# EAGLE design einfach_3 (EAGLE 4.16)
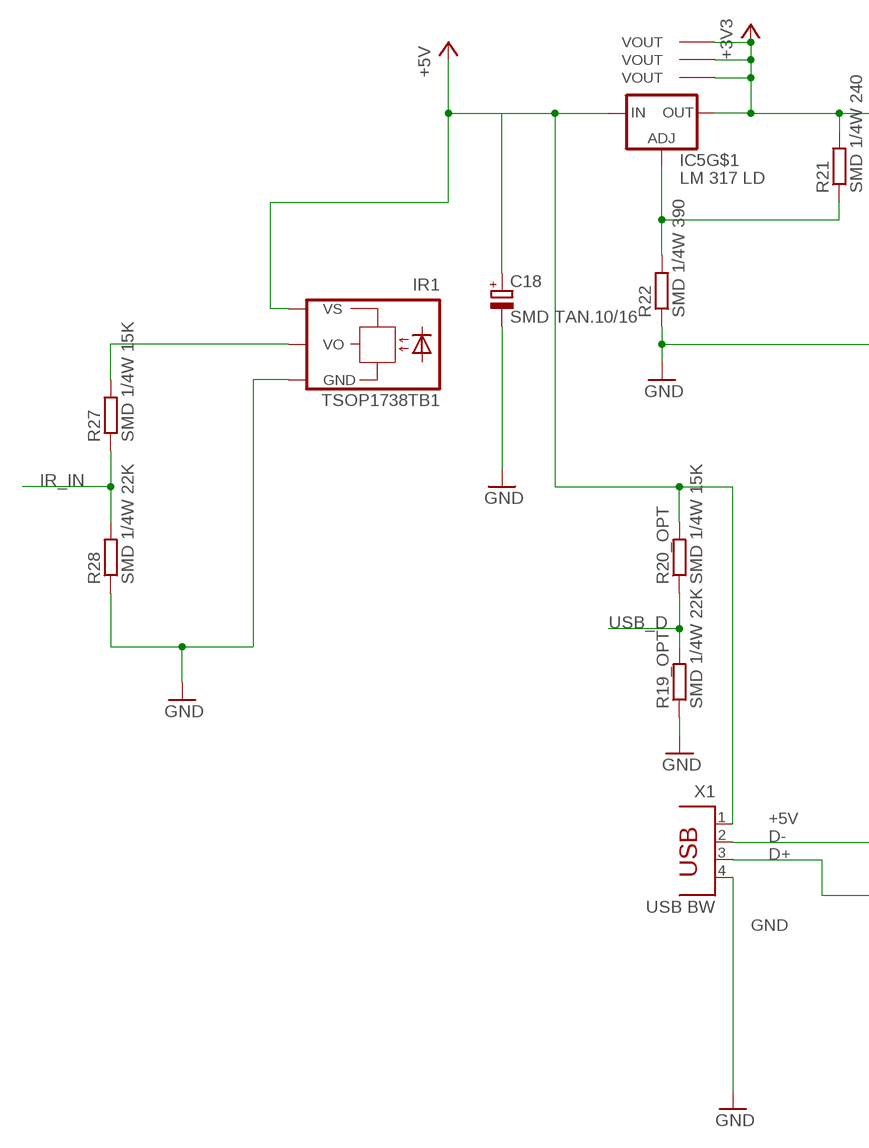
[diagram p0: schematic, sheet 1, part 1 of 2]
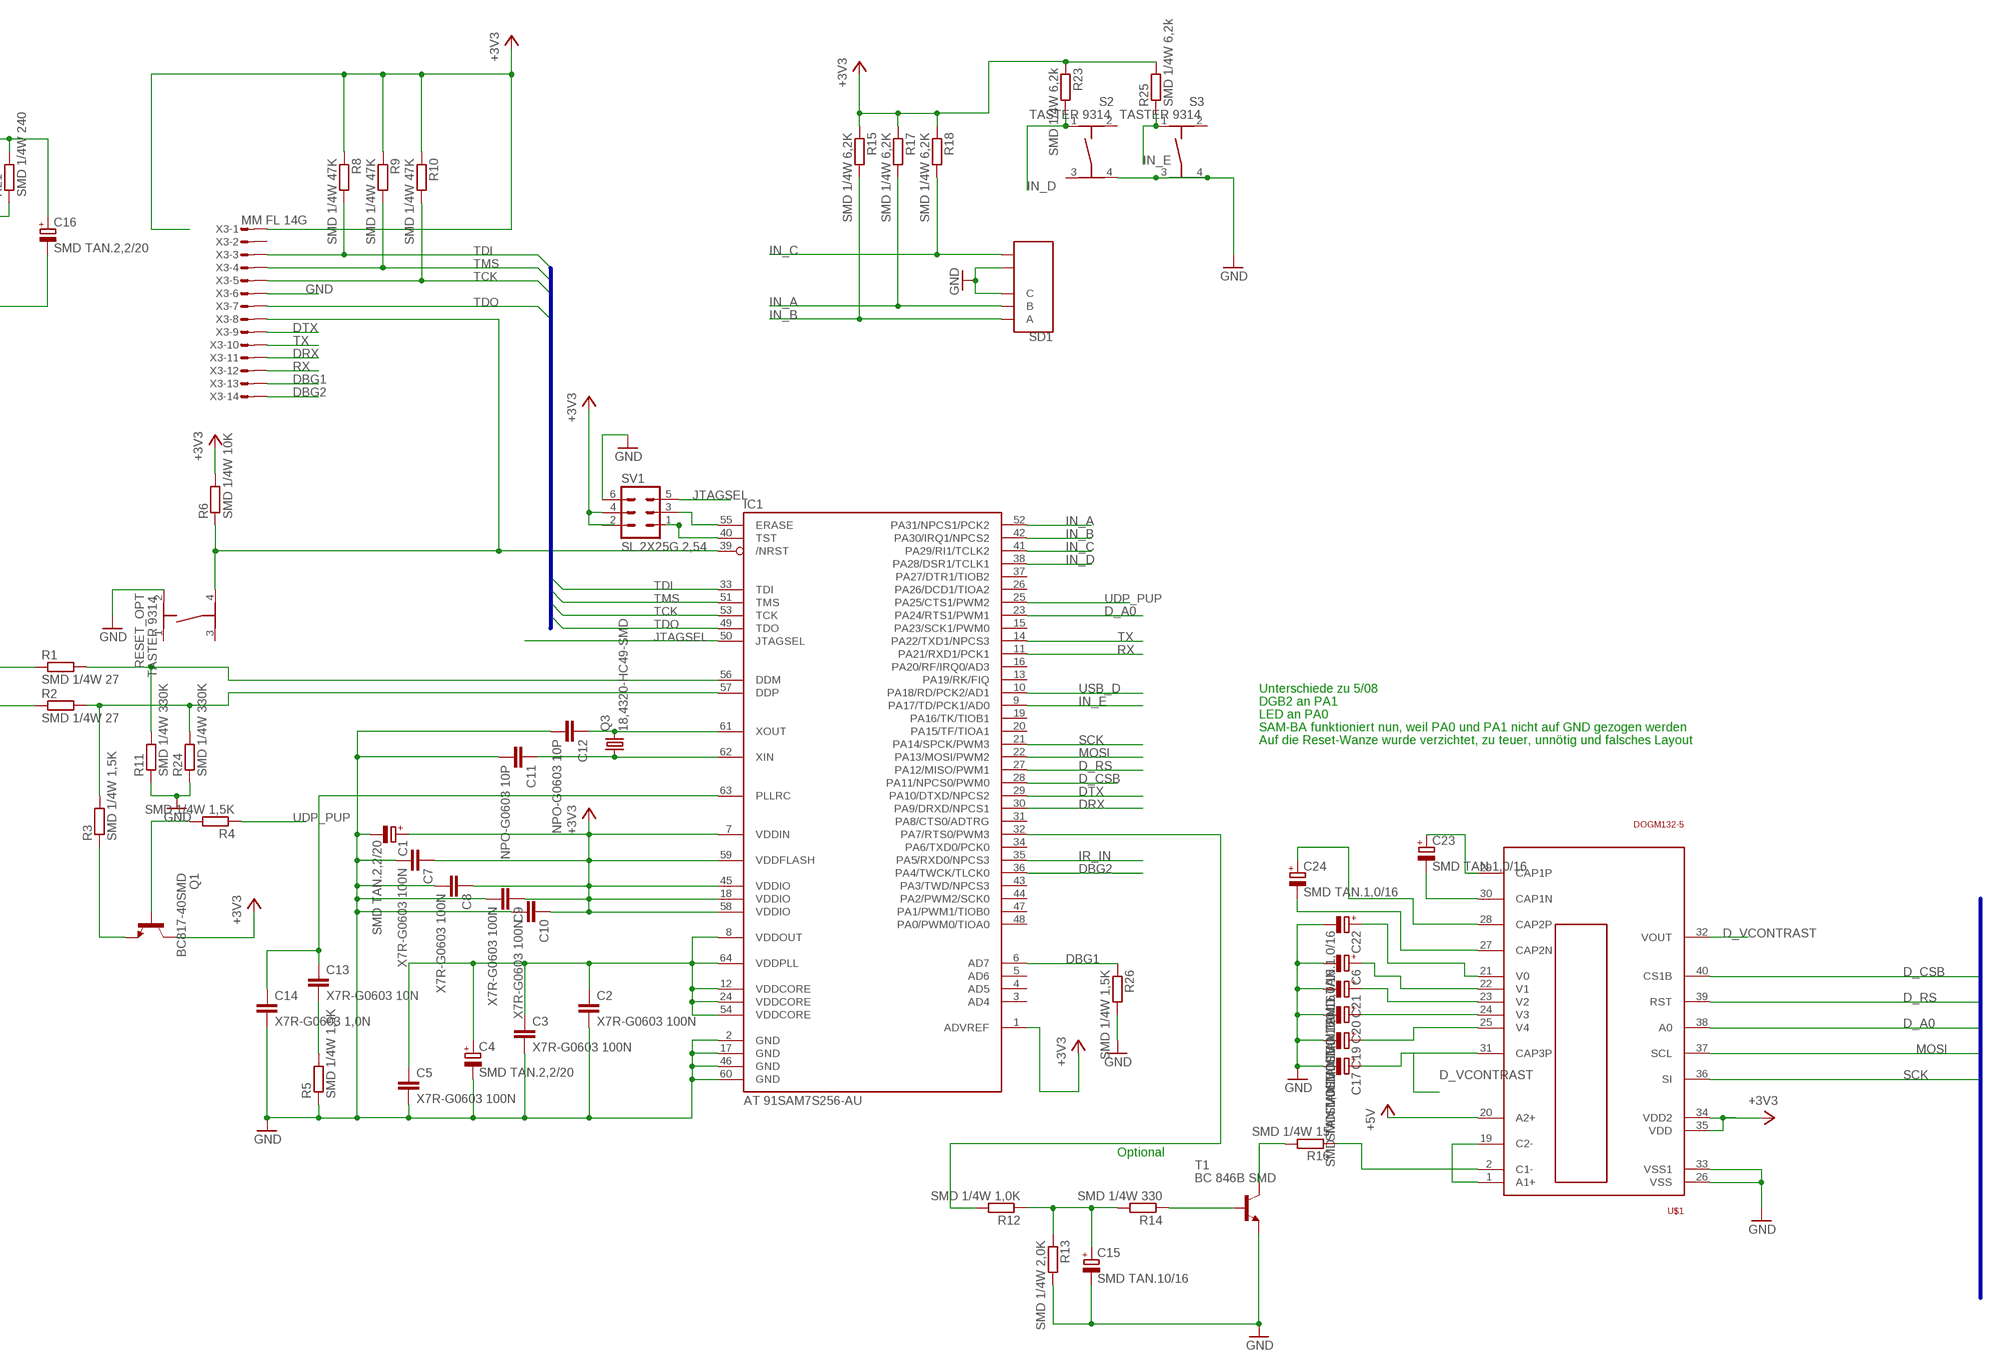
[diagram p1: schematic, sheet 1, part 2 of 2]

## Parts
C1  SMD TAN.2,2/20  CPOL-EUCT3528  [CT3528]
C2  X7R-G0603 100N  C-EUC0603  [C0603]
C3  X7R-G0603 100N  C-EUC0603  [C0603]
C4  SMD TAN.2,2/20  CPOL-EUCT3528  [CT3528]
C5  X7R-G0603 100N  C-EUC0603  [C0603]
C6  SMD TAN.1,0/16  CPOL-EUCT3216  [CT3216]
C7  X7R-G0603 100N  C-EUC0603  [C0603]
C8  X7R-G0603 100N  C-EUC0603  [C0603]
C9  X7R-G0603 100N  C-EUC0603  [C0603]
C10  X7R-G0603 100N  C-EUC0603  [C0603]
C11  NPO-G0603 10P  C-EUC0603  [C0603]
C12  NPO-G0603 10P  C-EUC0603  [C0603]
C13  X7R-G0603 10N  C-EUC0603  [C0603]
C14  X7R-G0603 1,0N  C-EUC0603  [C0603]
C15  SMD TAN.10/16  CPOL-EUCT7343  [CT7343]
C16  SMD TAN.2,2/20  CPOL-EUCT3528  [CT3528]
C17  SMD TAN.1,0/16  CPOL-EUCT3216  [CT3216]
C18  SMD TAN.10/16  CPOL-EUCT7343  [CT7343]
C19  SMD TAN.1,0/16  CPOL-EUCT3216  [CT3216]
C20  SMD TAN.1,0/16  CPOL-EUCT3216  [CT3216]
C21  SMD TAN.1,0/16  CPOL-EUCT3216  [CT3216]
C22  SMD TAN.1,0/16  CPOL-EUCT3216  [CT3216]
C23  SMD TAN.1,0/16  CPOL-EUCT3216  [CT3216]
C24  SMD TAN.1,0/16  CPOL-EUCT3216  [CT3216]
IC1  AT 91SAM7S256-AU  AT91SAM7S512/256/128/64/321  [LQFP64_GOOD]
IC5  LM 317 LD  LM317-SO08  [SO-08]
IR1  TSOP1738TB1  [TSOP17_TB1]
Q1  BC817-40SMD  [SOT23-BEC]
Q3  18,4320-HC49-SMD  CRYSTALHC49UP  [HC49UP]
R1  SMD 1/4W 27  R-EU_R1206W  [R1206W]
R2  SMD 1/4W 27  R-EU_R1206W  [R1206W]
R3  SMD 1/4W 1,5K  R-EU_R1206W  [R1206W]
R4  SMD 1/4W 1,5K  R-EU_R1206W  [R1206W]
R5  SMD 1/4W 1,5K  R-EU_R1206W  [R1206W]
R6  SMD 1/4W 10K  R-EU_R1206W  [R1206W]
R8  SMD 1/4W 47K  R-EU_R1206W  [R1206W]
R9  SMD 1/4W 47K  R-EU_R1206W  [R1206W]
R10  SMD 1/4W 47K  R-EU_R1206W  [R1206W]
R11  SMD 1/4W 330K  R-EU_R1206W  [R1206W]
R12  SMD 1/4W 1,0K  R-EU_R1206W  [R1206W]
R13  SMD 1/4W 2,0K  R-EU_R1206W  [R1206W]
R14  SMD 1/4W 330  R-EU_R1206W  [R1206W]
R15  SMD 1/4W 6,2K  R-EU_R1206W  [R1206W]
R16  SMD 1/4W 15  R-EU_R1206W  [R1206W]
R17  SMD 1/4W 6,2K  R-EU_R1206W  [R1206W]
R18  SMD 1/4W 6,2K  R-EU_R1206W  [R1206W]
R19_OPT  SMD 1/4W 22K  R-EU_R1206W  [R1206W]
R20_OPT  SMD 1/4W 15K  R-EU_R1206W  [R1206W]
R21  SMD 1/4W 240  R-EU_R1206W  [R1206W]
R22  SMD 1/4W 390  R-EU_R1206W  [R1206W]
R23  SMD 1/4W 6,2k  R-EU_R1206W  [R1206W]
R24  SMD 1/4W 330K  R-EU_R1206W  [R1206W]
R25  SMD 1/4W 6,2k  R-EU_R1206W  [R1206W]
R26  SMD 1/4W 1,5K  R-EU_R1206W  [R1206W]
R27  SMD 1/4W 15K  R-EU_R1206W  [R1206W]
R28  SMD 1/4W 22K  R-EU_R1206W  [R1206W]
RESET_OPT  TASTER 9314  TASTER-9314_SMD  [TASTER-9314_SMD]
S2  TASTER 9314  TASTER-9314_SMD  [TASTER-9314_SMD]
S3  TASTER 9314  TASTER-9314_SMD  [TASTER-9314_SMD]
SD1  STEC12E08  STEC12D08  [EC12E08]
SV1  SL 2X25G 2,54  MA03-2  [MA03-2]
T1  BC 846B SMD  BC846  [SOT23]
U$1  DOGM132-5  [DOGM]
X1  USB BW  PN61729  [PN61729]
X3  MM FL 14G  MICROMATCH-14  [MICROMATCH-14]

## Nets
1.8V: C2.1 C3.1 C4.+ C5.1 IC1.8(VDDOUT) IC1.12(VDDCORE) IC1.24(VDDCORE) IC1.54(VDDCORE) IC1.64(VDDPLL)
+3V3: C1.+ C7.1 C8.1 C9.1 C10.1 C16.+ IC1.1(ADVREF) IC1.7(VDDIN) IC1.18(VDDIO) IC1.45(VDDIO) IC1.58(VDDIO) IC1.59(VDDFLASH) IC5.2(OUT) IC5.3(VOUT) IC5.6(VOUT) IC5.7(VOUT) Q1.C R6.2 R8.1 R9.1 R10.1 R15.1 R17.1 R18.1 R21.2 R23.1 R25.2 SV1.2 SV1.4 U$1.34(VDD2) U$1.35(VDD) X3.1
+5V: C18.+ IC5.1(IN) IR1.VS R20_OPT.2 U$1.20(A2+) X1.1
D+: R2.1 X1.3
D-: R1.1 X1.2
D_A0: IC1.23(PA24/RTS1/PWM1) U$1.38(A0)
D_CSB: IC1.28(PA11/NPCS0/PWM0) U$1.40(CS1B)
D_RS: IC1.27(PA12/MISO/PWM1) U$1.39(RST)
D_VCONTRAST: C17.+ U$1.31(CAP3P) U$1.32(VOUT)
DBG1: IC1.6(AD7) R26.1 X3.13
DBG2: IC1.36(PA4/TWCK/TLCK0) X3.14
DDM: IC1.56(DDM) R1.2 R11.2
DDP: IC1.57(DDP) R2.2 R3.2 R24.2
DRX: IC1.30(PA9/DRXD/NPCS1) X3.11
DTX: IC1.29(PA10/DTXD/NPCS2) X3.9
GND: C1.- C2.2 C3.2 C4.- C5.2 C6.- C7.2 C8.2 C9.2 C10.2 C11.2 C12.2 C14.2 C15.- C16.- C17.- C18.- C19.- C20.- C21.- C22.- IC1.2(GND) IC1.17(GND) IC1.46(GND) IC1.60(GND) IR1.GND R5.1 R11.1 R13.2 R19_OPT.1 R22.1 R24.1 R26.2 R28.1 RESET_OPT.2 S2.4 S3.3 S3.4 SD1.C SD1.D(S1) SV1.6 T1.2(E) U$1.26(VSS) U$1.33(VSS1) X1.4 X3.6
IN_A: IC1.52(PA31/NPCS1/PCK2) R17.2 SD1.B
IN_B: IC1.42(PA30/IRQ1/NPCS2) R15.2 SD1.A
IN_C: IC1.41(PA29/RI1/TCLK2) R18.2 SD1.E(S2)
IN_D: IC1.38(PA28/DSR1/TCLK1) R23.2 S2.1
IN_E: IC1.9(PA17/TD/PCK1/AD0) R25.1 S3.1
IR_IN: IC1.35(PA5/RXD0/NPCS3) R27.1 R28.2
JTAGSEL: IC1.50(JTAGSEL) SV1.5
LED: IC1.32(PA7/RTS0/PWM3) R12.2
MOSI: IC1.22(PA13/MOSI/PWM2) U$1.36(SI)
N$1: U$1.1(A1+) U$1.19(C2-)
N$2: R16.1 U$1.2(C1-)
N$3: Q1.E R3.1
N$4: Q1.B R4.2
N$5: IR1.VO R27.2
N$6: IC1.40(TST) SV1.1
N$7: C11.1 IC1.62(XIN) Q3.1
N$8: C12.1 IC1.61(XOUT) Q3.2
N$9: C13.1 C14.1 IC1.63(PLLRC)
N$10: C13.2 R5.2
N$11: IC1.39(/NRST) R6.1 RESET_OPT.4 X3.8
N$12: IC1.55(ERASE) SV1.3
N$13: C6.+ U$1.22(V1)
N$14: C19.+ U$1.25(V4)
N$15: C20.+ U$1.24(V3)
N$16: C21.+ U$1.23(V2)
N$17: C22.+ U$1.21(V0)
N$21: C24.+ U$1.28(CAP2P)
N$22: C24.- U$1.27(CAP2N)
N$23: C23.- U$1.30(CAP1N)
N$24: C23.+ U$1.29(CAP1P)
N$31: R16.2 T1.3(C)
N$32: R14.1 T1.1(B)
N$33: C15.+ R12.1 R13.1 R14.2
N$40: IC5.4(ADJ) R21.1 R22.2
RX: IC1.11(PA21/RXD1/PCK1) X3.12
SCK: IC1.21(PA14/SPCK/PWM3) U$1.37(SCL)
TCK: IC1.53(TCK) R10.2 X3.5
TDI: IC1.33(TDI) R8.2 X3.3
TDO: IC1.49(TDO) X3.7
TMS: IC1.51(TMS) R9.2 X3.4
TX: IC1.14(PA22/TXD1/NPCS3) X3.10
UDP_PUP: IC1.25(PA25/CTS1/PWM2) R4.1
USB_D: IC1.10(PA18/RD/PCK2/AD1) R19_OPT.2 R20_OPT.1
Unconnected: IC1.3(AD4) IC1.4(AD5) IC1.5(AD6) IC1.13(PA19/RK/FIQ) IC1.15(PA23/SCK1/PWM0) IC1.16(PA20/RF/IRQ0/AD3) IC1.19(PA16/TK/TIOB1) IC1.20(PA15/TF/TIOA1) IC1.26(PA26/DCD1/TIOA2) IC1.31(PA8/CTS0/ADTRG) IC1.34(PA6/TXD0/PCK0) IC1.37(PA27/DTR1/TIOB2) IC1.43(PA3/TWD/NPCS3) IC1.44(PA2/PWM2/SCK0) IC1.47(PA1/PWM1/TIOB0) IC1.48(PA0/PWM0/TIOA0) RESET_OPT.1 RESET_OPT.3 S2.2 S2.3 S3.2 X3.2

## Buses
B$1
B$2

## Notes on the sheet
- Unterschiede zu 5/08
- DGB2 an PA1
- LED an PA0
- SAM-BA funktioniert nun, weil PA0 und PA1 nicht auf GND gezogen werden
- Auf die Reset-Wanze wurde verzichtet, zu teuer, unnötig und falsches Layout
- Optional

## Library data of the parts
C1 C4 C6 C15-C24 = rcl:CPOL-EU: POLARIZED CAPACITOR, European symbol
C2 C3 C5 C7-C14 = rcl:C-EU: CAPACITOR, European symbol
IC1 = at91sam7sxxx-au:AT91SAM7S512/256/128/64/321
IC5 = v-reg:LM317-SO08
IR1 = telefunken:TSOP17*TB1: TSOP17..TB1 IR Receiver Modules for Remote Control Systems Source: http://www.vishay.com/docs/82042/82042.pdf
Q1 = transistor-npn:BC817*: NPN Transistor
Q3 = crystal:CRYSTAL: CRYSTAL
R1-R6 R8-R18 R19_OPT R20_OPT R21-R28 = rcl:R-EU_: RESISTOR, European symbol
RESET_OPT S2 S3 = Ergaenzung:TASTER-9314_SMD
SD1 = piher:STEC12D08
SV1 = con-lstb:MA03-2: PIN HEADER
T1 = transistor:BC846: NPN TRANSISTOR
U$1 = opto:DOGM132-5
X1 = con-berg:PN61729: BERG USB connector
X3 = con-amp-micromatch:MICROMATCH-14: MicroMaTch 14 8-215464-4 / 1-215464-4 Drawing Number C-215464 DDEController.pdf

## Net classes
0 default: width 0.203 mm, drill 0.203 mm, clearance 0.6 mm
1 GND: width 0.203 mm, drill 0.203 mm, clearance 0.6 mm

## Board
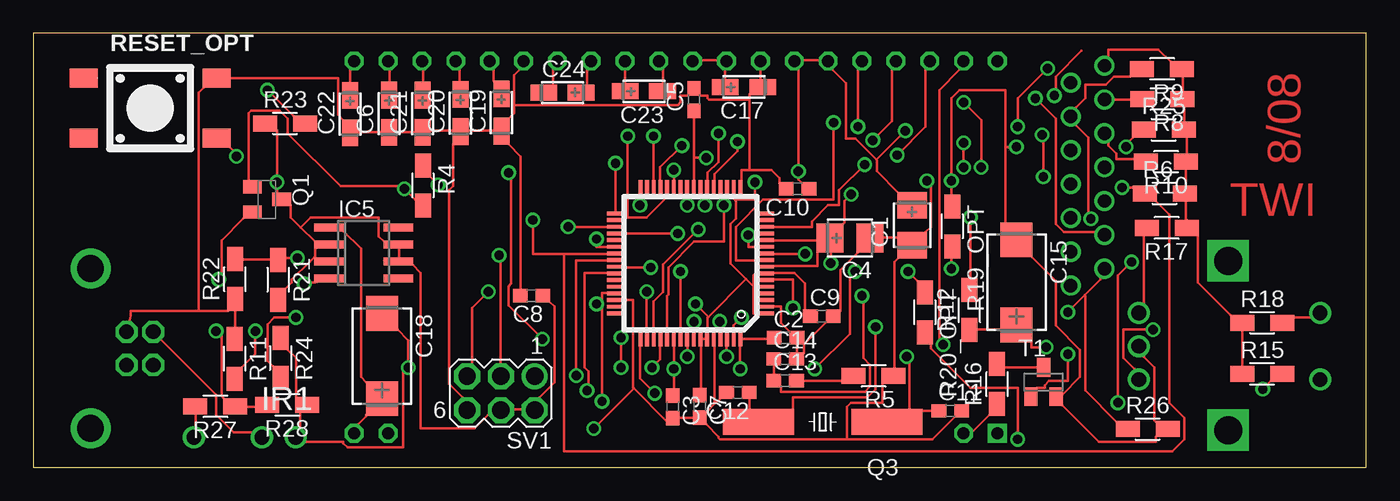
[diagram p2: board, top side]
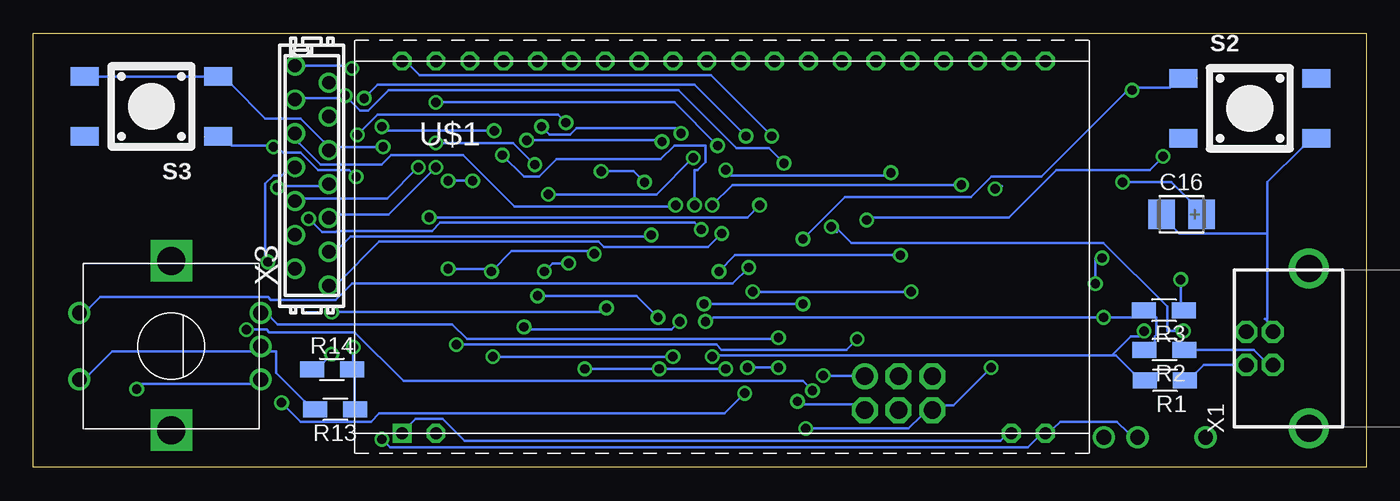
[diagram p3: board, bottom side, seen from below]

Size 100 x 32.6 mm. Coordinates in mm from the lower left corner, seen from the top.
Outline: 0,0 100,0 100,32.6 0,32.6 0,0
Copper layers (1*16): Top 0.035mm / dielectric 1.5mm / Bottom 0.035mm
Design rules "8mils": minimum track width 8mil, minimum drill 0.7mm, track to track 8mil, track to pad 8mil, pad to pad 8mil, via to via 8mil, smd to smd 8mil, copper to edge 40mil, drill to drill 10mil, minimum pad ring 10mil, minimum via ring 8mil, stop-mask expansion 0mil, vias tented up to drill 0mil, thermal gap 10mil

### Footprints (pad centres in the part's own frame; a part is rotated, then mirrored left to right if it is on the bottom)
CT3528 = smd 2 x 2.2: + 1.5,0; - -1.5,0
C0603 = smd 1.1 x 1: 1 -0.85,0; 2 0.85,0
CT3216 = smd 2 x 1.2: + 1.4,0; - -1.4,0
CT7343 = smd 2.6 x 2.4: + 3.2,0; - -3.2,0
LQFP64_GOOD = smd 1.1 x 0.285: 1 -5.7,3.75; 2 -5.7,3.25; 3 -5.7,2.75; 4 -5.7,2.25; 5 -5.7,1.75; 6 -5.7,1.25; 7 -5.7,0.75; 8 -5.7,0.25; 9 -5.7,-0.25; 10 -5.7,-0.75; 11 -5.7,-1.25; 12 -5.7,-1.75; 13 -5.7,-2.25; 14 -5.7,-2.75; 15 -5.7,-3.25; 16 -5.7,-3.75; 33 5.7,-3.75; 34 5.7,-3.25; 35 5.7,-2.75; 36 5.7,-2.25; 37 5.7,-1.75; 38 5.7,-1.25; 39 5.7,-0.75; 40 5.7,-0.25; 41 5.7,0.25; 42 5.7,0.75; 43 5.7,1.25; 44 5.7,1.75; 45 5.7,2.25; 46 5.7,2.75; 47 5.7,3.25; 48 5.7,3.75 | smd 0.285 x 1.1: 17 -3.75,-5.7; 18 -3.25,-5.7; 19 -2.75,-5.7; 20 -2.25,-5.7; 21 -1.75,-5.7; 22 -1.25,-5.7; 23 -0.75,-5.7; 24 -0.25,-5.7; 25 0.25,-5.7; 26 0.75,-5.7; 27 1.25,-5.7; 28 1.75,-5.7; 29 2.25,-5.7; 30 2.75,-5.7; 31 3.25,-5.7; 32 3.75,-5.7; 49 3.75,5.7; 50 3.25,5.7; 51 2.75,5.7; 52 2.25,5.7; 53 1.75,5.7; 54 1.25,5.7; 55 0.75,5.7; 56 0.25,5.7; 57 -0.25,5.7; 58 -0.75,5.7; 59 -1.25,5.7; 60 -1.75,5.7; 61 -2.25,5.7; 62 -2.75,5.7; 63 -3.25,5.7; 64 -3.75,5.7
SO-08 = smd 0.6 x 2.2: 1 -1.905,-2.6; 2 -0.635,-2.6; 3 0.635,-2.6; 4 1.905,-2.6; 5 1.905,2.6; 6 0.635,2.6; 7 -0.635,2.6; 8 -1.905,2.6
TSOP17_TB1 = drill 1.1 pad 1.676 round: GND 0,-3.81; VO 0,3.81; VS 0,-1.27
SOT23-BEC = smd 1 x 1.4: B -0.95,-1.1; C 0,1.1; E 0.95,-1.1
HC49UP = smd 5.334 x 1.93: 1 -4.826,0; 2 4.826,0
R1206W = smd 1.8 x 1.2: 1 -1.499,0; 2 1.499,0
TASTER-9314_SMD = smd 2.1 x 1.4: 1 -5,2.25; 2 5,2.25; 3 -5,-2.25; 4 5,-2.25
EC12E08 = drill 1.1 round: A -2.5,-6.7; B 2.5,-6.7; C 0,-6.7; D -2.5,6.9; E 2.5,6.9 | drill 2.1 square: P$1 -6.3,0; P$2 6.4,0
MA03-2 = drill 1.3 round: 1 -2.54,-1.27 | drill 1.3 octagon: 2 -2.54,1.27; 3 0,-1.27; 4 0,1.27; 5 2.54,-1.27; 6 2.54,1.27
SOT23 = smd 1 x 1.4: 1 -0.95,-1.1; 2 0.95,-1.1; 3 0,1.1
DOGM = drill 0.9 square: 1 -22.86,-13.97 | drill 0.9 octagon: 2 -20.32,-13.97; 19 22.86,-13.97; 20 25.4,-13.97; 21 25.4,13.97; 22 22.86,13.97; 23 20.32,13.97; 24 17.78,13.97; 25 15.24,13.97; 26 12.7,13.97; 27 10.16,13.97; 28 7.62,13.97; 29 5.08,13.97; 30 2.54,13.97; 31 0,13.97; 32 -2.54,13.97; 33 -5.08,13.97; 34 -7.62,13.97; 35 -10.16,13.97; 36 -12.7,13.97; 37 -15.24,13.97; 38 -17.78,13.97; 39 -20.32,13.97; 40 -22.86,13.97
PN61729 = drill 1.1 octagon: 1 1.25,4.71; 2 -1.25,4.71; 3 -1.25,2.71; 4 1.25,2.71 | drill 2 round: P$1 -6,0; P$2 6,0
MICROMATCH-14 = drill 1 round: 1 8.255,1.27; 2 6.985,-1.27; 3 5.715,1.27; 4 4.445,-1.27; 5 3.175,1.27; 6 1.905,-1.27; 7 0.635,1.27; 8 -0.635,-1.27; 9 -1.905,1.27; 10 -3.175,-1.27; 11 -4.445,1.27; 12 -5.715,-1.27; 13 -6.985,1.27; 14 -8.255,-1.27

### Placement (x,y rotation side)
C1  65.93,18.19 90 top
C2  56.44,9.74 0 top
C3  47.98,4.56 270 top
C4  61.27,17.23 180 top
C5  49.57,27.62 90 top
C6  26.69,26.56 90 top
C7  49.99,4.6 270 top
C8  37.38,12.91 180 top
C9  59.15,11.37 0 top
C10  57.35,20.92 180 top
C11  68.79,4.25 0 top
C12  52.86,5.64 180 top
C13  56.41,6.52 0 top
C14  56.41,8.15 0 top
C15  73.76,13.91 270 top
C16  13.85,19.01 0 bottom
C17  53.32,28.57 180 top
C18  26.15,8.36 270 top
C19  35.11,26.66 90 top
C20  32.04,26.62 90 top
C21  29.21,26.56 90 top
C22  23.77,26.53 90 top
C23  45.81,28.24 180 top
C24  39.69,28.14 0 top
IC1  49.3,15.33 180 top
IC5  24.78,16.11 270 top
IR1  15.87,2.27 90 top
Q1  17.53,20.13 270 top
Q3  59.22,3.42 180 top
R1  15.1,6.55 180 bottom
R2  15.15,8.85 180 bottom
R3  15.18,11.8 180 bottom
R4  29.23,21.17 270 top
R5  63.02,6.88 180 top
R6  84.88,20.59 0 top
R8  84.7,27.65 180 top
R9  84.68,29.92 180 top
R10  84.98,22.95 180 top
R11  15.1,8.16 270 top
R12  70.23,11.84 90 top
R13  77.34,4.37 180 bottom
R14  77.6,7.37 0 bottom
R15  92.2,7.04 0 top
R16  72.31,6.27 90 top
R17  85.03,17.99 180 top
R18  92.2,10.87 0 top
R19_OPT  68.94,18.08 270 top
R20_OPT  66.88,11.64 270 top
R21  18.36,14.09 270 top
R22  15.13,14.15 90 top
R23  18.89,25.84 0 top
R24  18.56,8.22 270 top
R25  84.81,25.36 0 top
R26  83.6,2.89 0 top
R27  13.66,4.59 180 top
R28  19.04,4.7 180 top
RESET_OPT  8.77,26.98 0 top
S2  8.73,26.96 0 bottom
S3  91.13,27.11 180 bottom
SD1  89.65,9.11 90 bottom
SV1  35.08,5.58 180 top
T1  75.79,6.42 0 top
U$1  49.47,16.55 0 bottom
X1  4.29,8.94 90 bottom
X3  79.1,21.91 90 bottom

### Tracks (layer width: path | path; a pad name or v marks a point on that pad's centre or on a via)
1.8V  (via drill 0.7)
  Top 0.203: C2.1 55.06,9.64 53.13,9.64 IC1.64 53.03,9.13 v53.03,7.4 | C3.1 48.05,5.88 v48.05,7.4 48.05,9.13 IC1.54 | 49.57,23.25 49.57,26.3 C5.1 | 49.57,23.25 49.57,21.53 IC1.24 | IC1.8 55.47,15.13 58.82,15.13 58.82,16.14 C4.+ | IC1.12 55.47,17.06 58.82,17.06 C4.+ | v50.49,23.25 49.57,23.25 | v61.36,20.51 60.85,20 60.85,18.38 60.75,18.28 C4.+ | v58.62,7.4 61.26,10.05 61.26,14.31 v61.66,14.72 | v59.84,15.33 59.84,16.14 C4.+
  Bottom 0.203: v48.05,7.4 v53.03,7.4 v58.62,7.4 | v50.49,23.25 53.23,20.51 v61.36,20.51 | v61.66,14.72 61.05,15.33 v59.84,15.33
+3V3  (via drill 0.7)
  Top 0.203: C8.1 38.7,12.48 39.11,12.08 39.11,6.39 37.99,5.27 SV1.2 36.67,4.36 35.96,4.36 SV1.4 34.13,3.95 33.12,2.93 29.05,2.93 29.05,14.62 28.44,15.23 IC5.6 | v42.67,4.97 42.67,12.28 | 42.67,12.28 42.67,13.09 43.07,13.09 IC1.45 | IC5.6 27.43,15.74 27.43,16.45 IC5.7 26.31,16.95 25.9,17.36 25.9,18.78 20.82,18.78 20.06,18.02 | IC5.6 26.31,15.53 | R15.1 90.72,7.61 90.72,10.35 R18.1 89.81,11.47 87.37,13.91 87.37,17.46 R17.1 | R17.1 86.56,18.58 | C7.1 50.08,5.98 50.08,9.13 IC1.58 50.18,9.64 50.49,9.64 IC1.59 50.59,10.15 50.59,11.27 50.64,11.32 | 54.05,13.6 54.05,14.41 54.25,14.62 54.45,14.62 IC1.7 55.47,14.62 57.09,14.62 57.91,13.81 57.91,11.77 C9.1 | 54.05,13.6 54.05,11.57 54.45,11.57 IC1.1 | 52.67,20.05 52.72,20 52.72,18.68 52.32,18.28 52.32,15.33 53.49,14.16 | 52.67,20.05 52.52,20.21 52.52,20.51 IC1.18 | 53.49,14.16 54.05,13.6 | 50.64,11.32 53.49,14.16 | C10.1 57.7,21.32 57.4,21.63 v57.4,22.24 57.4,29.86 U$1.34 57.7,30.57 59.02,30.57 U$1.35 59.94,29.86 60.95,28.84 60.95,24.68 61.66,24.68 63.24,23.1 | 63.24,23.1 63.29,23.05 63.29,22.24 64.92,20.61 C1.+ | v54.15,21.43 54.15,20.1 52.72,20.1 52.67,20.05 | v76.09,29.96 73.86,27.72 v73.86,25.59 | 63.24,23.1 v65.42,25.29 | 42.67,12.28 v42.26,12.28 | v49.68,12.28 50.64,11.32 | 21.08,15.79 21.13,15.84 21.13,16.45 IC5.2 21.13,16.95 20.06,18.02 | 21.08,15.79 20.77,15.48 | 20.77,15.48 19.4,14.11 19.4,13.91 18.89,13.4 R21.2 | 20.77,15.48 20.72,15.53 | IC5.3 21.13,15.74 21.08,15.79 | R17.1 86.46,18.58 86.46,20 R6.2 86.46,21.12 86.46,22.44 R10.1 86.56,23.46 86.56,24.78 R25.2 86.35,25.89 86.35,27.11 R8.1 86.25,28.23 86.25,29.35 R9.1 85.34,30.47 84.42,31.38 80.66,31.38 80.66,30.87 X3.1
  Top 0.203: R23.1 18.28,25.29 v18.28,21.43 18.28,20.61 Q1.C 19.3,19.7 19.3,18.78 20.06,18.02
  Bottom 0.203: v42.67,4.97 42.46,4.76 38.5,4.76 SV1.2 | v54.15,21.43 54.96,22.24 v57.4,22.24 | v73.86,25.59 73.55,25.29 v65.42,25.29 | v42.26,12.28 v49.68,12.28 | X3.1 79.65,30.16 76.6,30.16 v76.09,29.96 | v18.28,21.43 14.62,21.43 13.3,20.1 C16.+
+5V  (via drill 0.7)
  Top 0.203: v73.86,2.12 73.86,5.98 70.3,5.98 67.35,8.93 67.35,9.33 R20_OPT.2 | X1.1 9.34,9.84 13.71,5.47 13.71,3.95 15.03,2.63 16.35,2.63 IR1.VS | U$1.20 24.38,3.24 24.99,3.85 24.99,3.95 C18.+ 24.99,6.39 24.58,6.79 24.58,16.45 23.26,17.77 IC5.1
  Bottom 0.203: v73.86,2.12 73.25,1.51 25.39,1.51 24.68,2.22 U$1.20 23.46,2.93 22.95,3.44 18.69,3.44 17.88,2.63 IR1.VS
D+
  Bottom 0.203: R2.1 12.79,8.83 8.43,8.83 7.72,8.12 X1.3
D-
  Bottom 0.203: R1.1 12.79,7.1 12.19,7.71 9.75,7.71 X1.2
D_A0  (via drill 0.7)
  Top 0.203: v50.39,19.7 50.08,20 50.08,20.51 IC1.23 | v64.81,23.46 66.95,25.59 66.95,29.86 U$1.38
  Bottom 0.203: v50.39,19.7 50.39,22.34 50.18,22.34 49.57,22.95 49.57,24.17 51.91,24.17 52.93,23.15 60.75,23.15 62.07,21.83 63.19,21.83 v64.81,23.46
D_CSB  (via drill 0.7)
  Top 0.203: v44.6,24.88 44.6,18.78 46.02,18.78 47.54,20.31 47.54,20.51 IC1.28
  Bottom 0.203: v44.6,24.88 49.17,29.45 71.01,29.45 71.72,30.16 U$1.40
D_RS  (via drill 0.7)
  Top 0.203: v48.05,22.34 48.05,21.53 IC1.27 | v35.66,22.14 35.86,21.93 35.86,13.81 35.66,13.6 35.66,12.18 v38.2,9.64 | v68.27,9.23 67.96,9.54 67.96,28.33 69.49,29.86 U$1.39
  Bottom 0.203: v48.05,22.34 47.64,21.93 35.86,21.93 v35.66,22.14 | v38.2,9.64 39.01,8.83 48.35,8.83 48.76,9.23 v68.27,9.23
D_VCONTRAST
  Top 0.203: C17.+ 51.91,29.15 51.91,29.86 U$1.32 51.4,30.57 50.08,30.57 U$1.31
DBG1  (via drill 0.7)
  Top 0.203: v56.99,11.98 56.99,14.11 55.47,14.11 IC1.6 | 78.89,12.94 80.05,14.11 80.05,14.21 X3.13 | v77.62,11.67 78.89,12.94 | R26.1 81.27,3.44 78.94,5.78 78.94,12.89 78.89,12.94
  Bottom 0.203: v56.99,11.98 57.3,11.67 v77.62,11.67
DBG2  (via drill 0.7)
  Top 0.203: v48.35,17.56 44.09,17.56 IC1.36
  Bottom 0.203: v48.35,17.56 49.37,16.55 57.19,16.55 57.6,16.95 74.06,16.95 77.11,13.91 X3.14
DDM  (via drill 0.7)
  Top 0.203: v49.07,8.32 49.07,9.13 IC1.56 | v16.66,10.25 16.66,8.52 15.64,7.51 R11.2
  Bottom 0.203: 48.96,8.42 v49.07,8.32 48.56,8.42 19.09,8.42 | 19.09,8.42 18.79,8.42 17.47,7.1 R1.2 | v16.66,10.25 17.06,9.84 17.67,9.84 19.09,8.42
DDP  (via drill 0.7)
  Top 0.203: v49.57,10.96 49.57,10.15 IC1.57 | v19.7,11.27 18.08,11.27 17.57,10.76 17.57,8.01 17.98,7.61 R24.2
  Bottom 0.203: 49.27,11.27 v49.57,10.96 49.07,11.16 48.96,11.27 v19.7,11.27 17.57,11.27 R3.2 15.84,11.27 15.74,11.27 15.74,9.94 15.84,9.84 15.84,9.44 R2.2
DRX  (via drill 0.7)
  Top 0.203: v46.53,24.88 46.53,21.53 IC1.30 | v75.18,27.72 76.7,26.2 76.7,18.28 77.31,17.67 79.65,17.67 X3.11
  Bottom 0.203: v46.53,24.88 50.39,28.74 74.16,28.74 v75.18,27.72
DTX  (via drill 0.7)
  Top 0.203: v48.66,24.17 47.03,22.54 47.03,21.53 IC1.29 | v69.79,27.42 71.11,26.1 v71.11,22.54
  Bottom 0.203: v48.66,24.17 51.91,27.42 v69.79,27.42 | v71.11,22.54 73.45,20.21 79.65,20.21 X3.9
GND  (via drill 0.7)
  Top 0.203: 72.94,24.07 72.94,18.38 C15.- 74.87,15.84 76.7,14.01 76.7,10.66 78.53,8.83 78.53,6.79 77.21,5.47 T1.2 77.21,4.66 79.95,1.92 84.22,1.92 84.22,2.32 R26.2 84.22,3.44 84.12,3.54 84.12,7.51 83.31,8.32 SD1.C | 72.94,24.07 72.94,28.33 69.49,28.33 68.88,27.72 v68.88,21.53 68.88,20.41 R19_OPT.1 | 72.94,24.07 v73.76,24.07 | C7.2 49.57,3.75 48.46,3.75 C3.2 47.54,3.44 45.05,5.93 | 45.05,5.93 45,5.98 45,12.59 44.09,12.59 IC1.46 | 51.15,4.81 50.49,4.15 C7.2 | 51.15,4.81 51.5,5.17 C12.2 | IC1.60 51.1,9.13 51.1,4.86 51.15,4.81 | 61.05,2.12 67.46,2.12 69.18,3.85 C11.2 | 61.05,2.12 61.05,4.56 61.36,4.86 63.7,4.86 63.7,6.29 R5.1 64.61,7.4 64.61,15.43 64.92,15.74 C1.- | C1.- 64.92,17.26 63.7,17.26 C4.- 61.87,16.14 60.55,14.82 60.55,11.77 C9.2 59.53,10.96 57.8,9.23 57.8,8.62 C14.2 57.3,8.62 57.3,9.33 C2.2 56.79,10.15 56.08,10.86 56.08,12.08 55.47,12.08 IC1.2 | 61.05,2.12 51.5,2.12 51.4,2.22 51.4,2.32 50.49,3.24 C7.2 | 53.74,22.34 53.13,22.34 53.13,21.53 IC1.17 | 53.74,22.34 55.37,22.34 55.98,21.73 55.98,21.32 C10.2 | 53.74,27.62 50.69,27.62 50.59,27.72 50.59,27.93 49.98,27.93 C5.2 49.17,27.93 48.56,27.93 48.56,27.42 48.35,27.22 36.06,27.22 | 53.74,27.62 53.74,28.03 C17.- 54.55,29.15 U$1.33 | 53.74,27.62 53.74,22.34 | C8.2 36.57,13.4 36.57,23.36 35.66,24.27 C19.- | 36.06,27.22 36.06,26.61 35.66,26.2 C19.- | 36.06,27.22 36.06,29.45 36.47,29.86 U$1.26 | C20.- 31.49,25.29 29.76,25.29 C21.- 28.64,25.18 27.22,25.18 C6.- 26.1,25.18 24.28,25.18 C22.- 23.26,26.1 22.85,26.5 22.85,29.25 14.73,29.25 RESET_OPT.2 12.79,28.54 12.39,28.13 12.39,11.77 | SV1.6 32.2,5.27 31.18,6.29 31.18,20.82 31.49,21.12 31.49,24.27 C20.-
  Top 0.203: C18.- 27.32,10.35 28.14,9.54 v28.14,7.51 27.73,7.2 27.73,1.51 23.56,1.51 23.26,1.82 23.26,1.92 20.41,1.92 IR1.GND 20.01,3.04 20.01,4.15 R28.1 19.7,5.27 19.7,8.22 19.09,8.83 R24.1 | C19.- 34.54,25.29 32.61,25.29 C20.- | v42.06,2.93 45.05,5.93 | v67.05,21.53 67.35,21.22 67.35,18.07 66.95,17.67 C1.- | R11.1 15.13,10.55 15.13,11.77 R22.1 14.62,11.77 12.39,11.77 | 12.39,11.77 7.31,11.77 7.31,11.37 X1.4
  Bottom 0.203: R13.2 79.65,4.97 81.78,7.1 81.78,8.72 82.19,8.72 SD1.C 83.71,8.72 94.08,8.72 95.8,7 SD1.D | v73.76,24.07 77.11,24.07 X3.6 78.23,24.47 79.95,26.2 82.59,26.2 85.13,28.74 S3.3 87.17,29.35 95.09,29.35 S3.4 | v28.14,7.51 30.98,4.66 31.59,4.66 SV1.6 33.42,3.85 34.33,2.93 v42.06,2.93 | v67.05,21.53 v68.88,21.53 | 7.61,11.16 7.51,11.16 7.49,11.12 | X1.4 7.49,11.12 | 7.41,17.56 7.41,11.16 7.49,11.12 | 7.41,17.56 7.41,21.43 4.77,24.07 S2.4 | 7.41,17.56 14.01,17.56 14.42,17.97 C16.-
IN_A  (via drill 0.7)
  Top 0.203: v46.42,7.51 47.03,8.12 47.03,9.13 IC1.52 | v44.09,7.51 v44.09,9.74 | R17.2 83.31,17.46 83.31,12.38 SD1.B
  Bottom 0.203: v44.09,7.51 v46.42,7.51 | v44.09,9.74 44.19,9.64 67.46,9.64 68.57,10.76 81.68,10.76 82.19,11.27 SD1.B
IN_B  (via drill 0.7)
  Top 0.203: v41.55,5.78 41.65,5.88 41.65,7.2 41.34,7.51 41.34,14.62 43.07,14.62 IC1.42 | v84.02,10.35 81.78,10.35 81.78,8.22 82.59,7.4 SD1.A | v92.25,5.88 92.86,6.49 R15.2
  Bottom 0.203: v41.55,5.78 42.26,6.49 72.23,6.49 75.89,10.15 82.29,10.15 82.49,10.35 v84.02,10.35 | v92.25,5.88 91.84,6.29 83.71,6.29 SD1.A
IN_C  (via drill 0.7)
  Top 0.203: v46.32,15.02 44.09,15.02 IC1.41 | R18.2 94.58,11.27 95.8,11.27 SD1.E
  Bottom 0.203: v46.32,15.02 47.54,13.81 76.09,13.81 77.31,12.59 82.19,12.59 82.39,12.79 94.99,12.79 95.8,11.98 SD1.E
IN_D  (via drill 0.7)
  Top 0.203: v42.26,17.16 42.26,16.55 43.07,16.55 IC1.38 | v17.57,28.33 19.5,26.4 R23.2
  Bottom 0.203: v42.26,17.16 39.11,20.31 29.66,20.31 28.14,21.83 24.38,21.83 18.08,28.13 v17.57,28.33 17.37,28.54 14.73,28.54 S2.1
IN_E  (via drill 0.7)
  Top 0.203: v60.04,25.89 60.04,20.1 54.76,20.1 52.72,18.07 52.72,15.53 54.45,15.53 IC1.9 | v75.69,24.98 75.79,24.88 v75.79,21.83 | v81.98,24.07 81.98,24.27 82.49,24.78 R25.1
  Bottom 0.203: v60.04,25.89 60.65,26.5 74.16,26.5 v75.69,24.98 | v75.79,21.83 76.3,22.34 78.63,22.34 79.95,23.66 81.27,23.66 81.48,23.86 v81.98,24.07 82.09,24.17 85.13,24.17 S3.1
IR_IN  (via drill 0.7)
  Top 0.203: v40.13,18.07 43.07,18.07 IC1.35 | R28.2 16.66,4.56 16.05,4.56 R27.1 14.32,5.17 14.12,5.37 14.12,9.84 v13.71,10.25
  Bottom 0.203: 39.72,17.67 v40.13,18.07 39.62,17.87 38.6,16.85 19.7,16.85 14.93,12.08 14.93,10.25 v13.71,10.25
JTAGSEL  (via drill 0.7)
  Top 0.203: v46.02,13.2 46.02,10.15 IC1.50 | v34.13,13.2 32.91,11.98 32.91,7.81 SV1.5
  Bottom 0.203: v34.13,13.2 v46.02,13.2
LED  (via drill 0.7)
  Top 0.203: v45.51,19.7 45.51,20.51 IC1.32 | v70.3,18.78 70.3,14.21 R12.2
  Bottom 0.203: v45.51,19.7 46.42,18.78 v70.3,18.78
MOSI  (via drill 0.7)
  Top 0.203: v51.4,25.08 51.4,22.95 50.59,22.14 50.59,21.53 IC1.22 | v61.87,25.59 61.87,29.86 U$1.36
  Bottom 0.203: v51.4,25.08 51.81,25.49 59.23,25.49 59.73,24.98 61.26,24.98 v61.87,25.59
N$1
  Bottom 0.203: U$1.19 27.22,2.22 27.43,2.02 67.66,2.02 69.29,3.65 71.32,3.65 71.72,3.24 U$1.1
N$2
  Top 0.203: R16.1 71.72,3.95 70.4,2.63 U$1.2
N$3  (via drill 0.7)
  Top 0.203: Q1.E 15.74,18.68 14.12,17.06 14.12,14.62 v13.91,14.11
  Bottom 0.203: v13.91,14.11 13.91,12.38 R3.1
N$4  (via drill 0.7)
  Top 0.203: R4.2 28.64,20.1 v27.83,20.92 27.32,21.12 23.06,21.12 19.09,25.08 19.09,26.2 18.48,26.81 16.35,26.81 16.15,26.61 16.15,21.53 Q1.B
  Bottom 0.203: v27.83,20.92 27.32,21.12
N$5
  Top 0.203: R27.2 12.19,4.05 12.19,3.04 IR1.VO
N$6  (via drill 0.7)
  Top 0.203: v40.73,6.9 40.73,15.53 43.07,15.53 IC1.40
  Bottom 0.203: v40.73,6.9 38.5,6.9 SV1.1
N$7  (via drill 0.7)
  Top 0.203: C11.1 67.46,4.25 66.64,4.25 Q3.1 65.73,4.36 65.73,8.12 v65.53,8.32 | v52.01,8.32 52.01,9.13 IC1.62
  Bottom 0.203: v52.01,8.32 v65.53,8.32
N$8  (via drill 0.7)
  Top 0.203: C12.1 53.74,5.17 53.74,4.36 Q3.2 56.99,4.36 56.99,5.27 62.58,5.27 63.19,5.88 v63.19,10.55 | v51.5,10.96 51.5,10.15 IC1.61
  Bottom 0.203: v51.5,10.96 52.11,10.35 62.99,10.35 v63.19,10.55
N$9  (via drill 0.7)
  Top 0.203: C14.1 55.57,7.71 55.57,7 C13.1 56.08,6.08 56.08,5.68 62.38,5.68 62.78,6.08 62.78,7.71 62.27,8.22 62.27,12.79 v62.17,12.89 | v53.13,11.27 52.52,10.66 52.52,10.15 IC1.63
  Bottom 0.203: v53.13,11.27 54.76,12.89 v62.17,12.89
N$10
  Top 0.203: C13.2 57.8,6.49 60.65,6.49 R5.2
N$11  (via drill 0.7)
  Top 0.203: 39.82,16.04 37.48,16.04 v37.48,18.58 | 39.82,16.04 43.07,16.04 IC1.39 | 39.82,16.04 39.82,1.21 85.44,1.21 86.35,2.12 86.35,3.75 85.24,4.86 85.24,18.99 84.22,20 R6.1 82.49,21.02 v81.68,21.02 | v15.23,23.36 15.23,23.56 14.73,24.07 RESET_OPT.4
  Bottom 0.203: 78.53,21.43 X3.8 78.53,21.12 81.58,21.12 v81.68,21.02 | 37.28,18.78 v37.48,18.58 36.98,18.78 26.82,18.78 23.26,22.34 16.25,22.34 v15.23,23.36
N$12  (via drill 0.7)
  Top 0.203: v48.56,14.72 48.56,10.15 IC1.55 | v34.94,15.94 35.05,15.84 35.05,7.81 SV1.3
  Bottom 0.203: v48.56,14.72 47.34,15.94 v34.94,15.94
N$13
  Top 0.203: C6.+ 26.71,28.94 26.71,29.86 U$1.22
N$14
  Top 0.203: C19.+ 34.54,29.05 34.54,29.86 U$1.25
N$15
  Top 0.203: C20.+ 32,28.94 32,29.86 U$1.24
N$16
  Top 0.203: C21.+ 29.25,28.94 29.25,29.86 U$1.23
N$17
  Top 0.203: C22.+ 23.77,29.86 U$1.21
N$21
  Top 0.203: C24.+ 41.55,28.64 41.55,29.86 U$1.28
N$22
  Top 0.203: C24.- 39.01,28.64 39.01,29.86 U$1.27
N$23
  Top 0.203: C23.- 47.24,28.74 47.24,29.86 U$1.30
N$24
  Top 0.203: C23.+ 44.39,28.74 U$1.29
N$31
  Top 0.203: T1.3 75.38,7.51 72.84,7.51 R16.2
N$32  (via drill 0.7)
  Top 0.203: v77.62,8.52 77.62,6.49 76.19,6.49 75.89,6.18 75.89,5.98 75.28,5.98 T1.1
  Bottom 0.203: v77.62,8.52 78.23,7.91 R14.1
N$33  (via drill 0.7)
  Top 0.203: R12.1 70.81,10.35 72.64,10.35 C15.+ 74.87,9.44 74.87,9.03 v75.99,9.03
  Bottom 0.203: R13.1 75.89,4.97 75.89,6.79 R14.2 75.99,7.91 v75.99,9.03
N$40  (via drill 0.7)
  Top 0.203: R22.2 15.64,15.63 17.77,15.63 R21.1 18.89,15.74 v19.81,15.74 | v20.31,13.81 20.31,13.91 21.13,13.91 IC5.4
  Bottom 0.203: v20.31,13.81 20.31,15.74 v19.81,15.74
RX  (via drill 0.7)
  Top 0.203: v53.64,17.46 53.64,16.55 54.45,16.55 IC1.11
  Bottom 0.203: v53.64,17.46 53.74,17.36 76.19,17.36 77.11,16.45 X3.12
SCK  (via drill 0.7)
  Top 0.203: v52.83,24.47 52.83,23.76 51.1,22.03 51.1,21.53 IC1.21 | v62.99,24.57 64.41,26 64.41,29.86 U$1.37
  Bottom 0.203: v52.83,24.47 52.93,24.57 v62.99,24.57
TCK  (via drill 0.7)
  Top 0.203: v51.81,19.7 51.81,16.95 49.57,16.95 47.64,15.02 47.64,12.99 47.54,12.89 47.54,10.15 IC1.53 | R10.2 82.59,23.15 81.27,23.15 81.27,23.56 80.66,24.17 80.66,24.37 X3.5
  Bottom 0.203: v51.81,19.7 51.91,19.6 63.9,19.6 67.76,23.46 73.15,23.46 73.86,22.75 78.43,22.75 80.05,24.37 X3.5
TDI  (via drill 0.7)
  Top 0.203: v43.68,22.85 43.68,19.19 IC1.33 | v76.6,27.93 76.7,28.03 76.7,29.35 78.63,31.28 | R8.2 82.39,27.62 81.07,27.62 X3.3
  Bottom 0.203: v43.68,22.85 44.8,23.96 47.24,23.96 51.61,28.33 73.35,28.33 74.87,26.81 75.48,26.81 v76.6,27.93 77.11,27.72 79.65,27.72 X3.3
TDO  (via drill 0.7)
  Top 0.203: v46.63,5.58 45.51,6.69 45.51,9.13 IC1.49 | v81.38,4.86 81.38,14.41 v82.39,15.43
  Bottom 0.203: v46.63,5.58 48.15,4.05 74.06,4.05 74.67,3.44 79.95,3.44 v81.38,4.86 | v82.39,15.43 82.59,15.43 82.59,21.32 81.98,21.93 81.38,21.93 81.07,22.24 X3.7
TMS  (via drill 0.7)
  Top 0.203: v49.88,17.87 47.24,15.23 47.24,13.2 46.53,12.48 46.53,10.15 IC1.51 | R9.2 82.29,29.35 81.07,29.35 80.46,28.74 78.94,28.74 78.94,27.72 78.23,27.01 X3.4 78.23,25.69 79.14,24.78 79.14,19.19 v79.34,18.68
  Bottom 0.203: v49.88,17.87 50.39,18.38 69.49,18.38 70.1,17.77 77.21,17.77 77.31,17.67 78.33,17.67 v79.34,18.68
TX  (via drill 0.7)
  Top 0.203: v62.38,22.75 60.45,20.82 60.45,19.7 59.63,19.7 58.41,18.48 58.41,18.07 55.47,18.07 IC1.14 | v69.79,24.37 v69.79,22.54
  Bottom 0.203: v62.38,22.75 64,24.37 v69.79,24.37 | v69.79,22.54 73.35,18.99 77.11,18.99 X3.10
UDP_PUP  (via drill 0.7)
  Top 0.203: v49.07,19.7 49.07,20.51 IC1.25 | v30.37,21.22 29.76,21.83 R4.1
  Bottom 0.203: v49.07,19.7 47.54,21.22 v30.37,21.22
USB_D  (via drill 0.7)
  Top 0.203: v57.91,16.04 55.47,16.04 IC1.10 | v65.63,14.72 66.34,14.01 R20_OPT.1 | v68.88,14.92 68.88,15.74 R19_OPT.2
  Bottom 0.203: v57.91,16.04 58.11,16.24 64.1,16.24 v65.63,14.72 66.14,14.92 v68.88,14.92

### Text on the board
Top: 8/08 | TWI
